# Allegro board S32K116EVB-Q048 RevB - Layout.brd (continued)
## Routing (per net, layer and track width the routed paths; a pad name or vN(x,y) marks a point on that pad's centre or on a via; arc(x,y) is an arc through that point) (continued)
XTAL: length 6.6
  TOP w0.16: Y3.2 57.34,26.25 57.82,25.77 C127.1 59.17,25.77 R91.2 R84.1
N20108236: length 2.2
  TOP w0.16: R737.1 39.52,35.43 38.99,34.91 U15.5
N20187731: length 2.1
  TOP w0.16: D11.A3 109.26,15.43 109.18,15.51 R95.1
N20187747: length 2.1
  TOP w0.16: R96.1 111.34,15.45 111.36,15.43 D11.A2
N20224636: length 10.2
  TOP w0.16: R597.1 C5.1 107.66,46.27 108.29,46.9 110.02,46.9 R13.2 108.41,43.98 TP5.1
N20296072: length 11
  TOP w0.16: R596.1 109.56,32.55 R44.1 SW2.3 SW2.1 112.27,38.78 112.23,38.82 TP532.1
N20296289: length 10.8
  TOP w0.16: R595.1 109.55,25.82 R74.1 SW3.1 ; SW3.1 SW3.3 ; SW3.1 112.27,26.96 112.23,27 TP531.1
N20296614: length 2.1
  TOP w0.16: D11.A1 113.46,15.43 113.5,15.47 R97.1
N20342040: length 5.5
  TOP w0.16: R712.2 R717.2 28.73,50.16 27.71,51.18 27.71,52.17 J2.10
N20342083: length 7.1
  TOP w0.16: J2.9 32.27,52.57 32.67,52.57 33.28,51.96 33.28,50.69 R719.2 R716.2 R713.2
N20408163: length 3.4
  TOP w0.203: TP540.1 33.11,32.68
  TOP w0.254: 33.11,32.68 R169.2 R170.2 35.17,32.71 U15.3
N20408770: length 1.6
  TOP w0.16: U15.4 40.06,32.71 40.06,32.71 C59.1
N20447644: length 3.5
  TOP w0.16: R675.2 73.68,51.38 73.62,51.45 J1.1
N20447648: length 3.9
  TOP w0.16: J1.2 72.16,52.3 R676.2
N20483097: length 2.5
  TOP w0.16: R715.2 J3.5
N20487701: length 2.6
  TOP w0.16: R527.1 SW8.1
N20498073: length 24.1
  TOP w0.203: v1(14.9,18.24) U19.15
  TOP w0.254: v1(33.74,19.98) 33.68,19.91 Q1.4
  BOTTOM w0.254: v1(14.9,18.24) 14.9,18.23 17.37,18.23 20.47,21.34 21.98,21.34 21.99,21.34 22.29,21.34 23.65,19.98 v1(33.74,19.98)
N20519466: length 3.5
  TOP w0.254: U19.13 15.88,19.24 15.87,19.25 14.95,19.25 TP544.1
  TOP w0.381: TP544.1 14.66,18.96 C536.1
N20529258: length 7.9
  TOP w0.508: D6.C 14.03,26.33 13.49,25.78 13.49,23.33 12.98,22.82 R171.2 R80.2
N20532266: length 36
  TOP w0.254: TP523.1 28.6,14.52 ; TP523.1 27.56,14.98 ; TP523.1 28.5,14.05 ; TP523.1 28.5,14.98 ; TP523.1 28.03,15.09 ; TP523.1 27.56,14.05 ; TP523.1 27.46,14.52
  TOP w0.305: 22.43,18.83 21.84,18.24 U19.6
  TOP w0.381: 22.88,18.88 R535.2 ; R535.2 22.88,19.52 ; R535.2 23.84,18.88 ; R535.2 24.79,19.52 ; R535.2 24.79,18.88
  TOP w0.635: Q1.5 30.64,20.38 ; Q1.5 28.05,15.62 ; Q1.5 30.64,18 ; Q1.5 25.46,15.63 ; Q1.5 25.46,20.38 ; Q1.5 28.05,20.39 ; Q1.5 30.64,15.63 ; Q1.5 25.46,18
  vias: v1(28.98,21.46)
N20533540: length 2.6
  TOP w0.16: R172.1 SW7.1
N20537015: length 24
  TOP w0.16: v1(9.61,13.36) C551.1 9.61,11.01 R537.2 SW9.1 SW9.3 2.15,11.88 TP518.1 ; U19.12 15.84,19.74 15.48,20.1 v1(14.95,20.1)
  L3_INT_1 w0.165: v1(9.61,13.36) 11.73,13.36 12.85,14.48 12.85,18.01 v1(14.95,20.1)
N20537534: length 3.6
  TOP w0.16: J108.1 17.38,21.93 D6.A
N20615858: length 2.7
  TOP w0.16: R612.2 R590.1 39.35,25.84 U26.6
N20615860: length 3
  TOP w0.16: U26.7 R589.1 38.19,27.22 R613.2
N20628442: length 2.4
  TOP w0.16: U32.7 R585.1 44.23,24.3 43.6,24.93 R616.2
N20629726: length 1.3
  TOP w0.16: U32.2 43.88,20.63 R577.2
N20726302: length 1.5
  TOP w0.16: U32.3 44.28,21.25 44.33,21.21 R578.2
N20727622: length 4.8
  TOP w0.16: v1(45.94,22.9) 45.55,22.52 U32.5 ; v1(43.21,23.09) 42.89,23.41 R562.2
  BOTTOM w0.16: v1(43.21,23.09) 43.4,22.9 v1(45.94,22.9)
N20728836: length 10.1
  TOP w0.16: C40.1 8.85,19.85 8.47,20.23 R92.2 5.63,20.23 5.22,19.82 5.22,16.93 5.73,16.42 R98.1
N20751108: length 1.4
  TOP w0.16: U33.5 R571.2
N20751111: length 2.4
  TOP w0.16: R610.2 49.24,24.93 R587.1 U33.7
N20751112: length 2.4
  TOP w0.16: U33.6 50.27,23.68 R588.1 R611.2
N20754157: length 1.4
  TOP w0.16: R572.2 40.6,24.68 U26.5
N20757133: length 2.1
  TOP w0.16: R615.2 R591.1 U34.7
N20757185: length 2.4
  TOP w0.16: U34.6 39.6,20 R592.1 R614.2
N20757257: length 1.2
  TOP w0.16: R576.2 U34.5
N20757373: length 2.7
  TOP w0.16: R617.2 R579.2 49.47,20.76 U33.2
N20757398: length 2.5
  TOP w0.16: U33.3 49.87,21.35 50.48,20.74 R580.2 50.63,20.61 R618.2
N20757820: length 3.4
  TOP w0.16: U26.2 38.55,23.64 38.37,23.46 37.38,23.46 R619.2 36.92,23.03 R581.2
N20757845: length 4
  TOP w0.16: U26.3 38.95,23.48 38.82,23.36 R582.2 39.71,22.9 40.6,23.79 R620.2
N20758005: length 2.7
  TOP w0.16: R621.2 37.68,17.82 R583.2 38.8,17.42 U34.2
N20758031: length 2.6
  TOP w0.16: U34.3 39.2,17.31 R584.2 40.04,17.06 40.27,17.28 R622.2
N20759089: length 1.4
  TOP w0.457: R56.2 D3.A
N20766439: length 4.5
  TOP w0.16: J14.6 80.83,45.9 80.63,46.1 R573.2 79.35,45.8 79.35,45.59 78.71,44.96 R119.1
N20766441: length 4.1
  TOP w0.16: R623.2 R120.1 80.59,47.73 81.15,47.17 J14.8
N20788275: length 3.8
  TOP w0.16: TPAD93.1 92.88,2.37 92.88,2.66 R598.2 R599.1 95.05,3.21 95.06,3.21 Q6.1
N20788431: length 3.4
  TOP w0.16: TPAD96.1 93.27,5.33 R601.2 R600.1 94.97,5.5 94.98,5.49 Q7.1
N20788562: length 4.8
  TOP w0.16: R603.2 R602.1 94.97,8.04 94.98,8.03 Q8.1 95.72,8.17 TPAD98.1
N20797138: length 3.9
  TOP w0.457: R605.1 47.21,15.4 Q9.1 48.34,16.05 48.48,16.19 TPAD100.1
  TOP w0.635: TPAD100.1 R604.2
N20798434: length 1.8
  TOP w0.457: Q9.3 49.63,14.38 D3.C
N20799004: length 4.1
  TOP w0.635: R606.1 v1(5.93,18.2)
  L3_INT_1 w0.635: J13.3 2.87,18.2 v1(5.93,18.2)
N20829527: length 2.1
  TOP w0.635: U15.1 36.66,34.61 37.3,35.25 R624.2
N20881340: length 4.9
  TOP w0.508: R674.2 107.99,51.47 R13.1
N20904035: length 25.5
  TOP w0.127: 74.28,24.38 U36.19
  TOP w0.16: R711.1 R740.1 v1(81.33,37.46) ; R739.1 v1(74.6,22.56) 74.14,23.02 74.14,23.66 74.28,23.8 74.28,24.38
  L3_INT_1 w0.165: v1(76.83,36.2) 76.48,35.84 76.48,24.86 75.89,24.28 75.89,23.8 74.65,22.56 v1(74.6,22.56)
  BOTTOM w0.16: v1(76.83,36.2) 80.06,36.2 v1(81.33,37.46)
N20906563: length 5.3
  TOP w0.16: J4.13 76.16,6.77 R685.2 R743.2
N20906569: length 4.8
  TOP w0.16: J4.11 73.62,6.41 R686.2
N20906587: length 4.9
  TOP w0.16: J4.5 64.67,6.45 64.67,8 63.65,9.02
N20906597: length 5.5
  TOP w0.16: J4.3 63.46,7.05 R742.2 R745.2
N20906792: length 40.7
  TOP w0.16: J4.15 78.7,4.26 77.68,3.24 77.68,2.16 78.28,1.56 80.45,1.56 81.18,2.29 81.18,5.33 83.21,7.37 83.21,9.02 v1(84.25,9.02) ; R681.2 84.21,31.41 v1(84.95,31.41)
  L3_INT_1 w0.165: v1(84.25,9.02) 83.64,9.63 83.64,19.91 82.95,20.6 82.95,24.82 84.95,26.81 v1(84.95,31.41)
N20910223: length 7.5
  TOP w0.16: 68.86,9.02 68.86,8.25 70,7.11 70,4.04 J4.8
N20910227: length 7.5
  TOP w0.16: R702.2 65.75,7.43 67.08,6.1 67.08,3.66 J4.6
N20911130: length 7.9
  TOP w0.16: R693.2 74.76,6.39 74.76,3.72 J4.12
N20911135: length 7.3
  TOP w0.16: J4.14 77.43,3.85 77.43,7.05 76.29,8.19 R694.2
N20911140: length 7.5
  TOP w0.16: J4.16 79.97,3.85 79.97,7.4 R695.2
N20917588: length 3.9
  TOP w0.16: J3.2 36.91,3.73 R754.2
N20917593: length 5.8
  TOP w0.16: R753.2 41.1,6.73 41.88,5.94 41.88,3.86 J3.4
N20917620: length 5.7
  TOP w0.16: R752.2 54.38,3.65 J3.14
N20992665: length 1.5
  TOP w0.16: R729.1 4.21,54.1 3.95,53.83 D1.A
N20992701: length 4.5
  TOP w0.16: R731.1 10.56,48.92 10.59,48.89 R730.1 10.59,47.57 10.72,47.45 10.72,46.61 10.54,46.43 9.35,46.43 9.18,46.6 Q10.3
N20992723: length 5.5
  TOP w0.16: R732.2 R733.2 12.57,45.09 11.81,44.32 9.93,44.32 9.68,44.58 Q10.5
N20992733: length 4.7
  TOP w0.16: Q11.2 7.19,45.77 9.42,48.01 R730.2 9.57,48.92 R734.1
N207179701: length 1.4
  TOP w0.635: C544.2 C545.1
N207665286: length 2.3
  TOP w0.16: J14.7 86.06,47.17 TP542.1
N207665288: length 2.3
  TOP w0.16: TP543.1 86.06,48.44 J14.9

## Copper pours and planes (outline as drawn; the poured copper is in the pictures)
GND on TOP: 0.77,39.01 2.27,39.01 2.68,39.43 2.68,42.28 2.37,42.6 0.77,42.6 0.76,45.34 2.46,45.34 2.67,45.55 2.67,47.11 2.51,47.27 0.76,47.27 0.76,49.53 3.14,55.28 8.89,57.66 106.71,57.66 112.45,55.28 114.83,49.53 114.83,8.89 112.45,3.14 106.71,0.76 8.92,0.76 3.17,3.14 0.79,8.89 ; 82 cut-outs
GND on BOTTOM: 0.77,39.01 2.27,39.01 2.68,39.43 2.68,42.28 2.37,42.6 0.77,42.6 0.76,45.34 2.46,45.34 2.67,45.55 2.67,47.11 2.51,47.27 0.76,47.27 0.76,49.53 3.14,55.28 8.89,57.66 79.2,57.66 79.2,52.55 79.6,52.15 103.08,52.15 103.09,52.16 104.08,52.16 108.17,48.07 108.17,11.57 106.29,9.7 89.2,9.7 85.38,5.88 81.75,5.88 81.75,2.03 64.06,2.03 63.88,1.85 63.88,0.76 8.92,0.76 3.17,3.14 0.79,8.89 ; 39 cut-outs
GND on L2_GND_1, L4_INT_2, L5_GND_2: 0.77,39.01 2.27,39.01 2.68,39.43 2.68,42.28 2.37,42.6 0.77,42.6 0.76,45.34 2.46,45.34 2.67,45.55 2.67,47.11 2.51,47.27 0.76,47.27 0.76,49.53 3.14,55.28 8.89,57.66 106.71,57.66 112.45,55.28 114.83,49.53 114.83,8.89 112.45,3.14 106.71,0.76 8.92,0.76 3.17,3.14 0.79,8.89
GND on L3_INT_1: 8.92,0.76 3.17,3.14 0.79,8.89 0.77,40.65 2.43,40.65 2.98,41.2 2.98,42.4 2.73,42.65 0.77,42.65 0.76,45.25 2.3,45.25 2.87,45.81 2.87,47.45 2.54,47.77 0.76,47.77 0.76,48.83 1.13,48.83 1.13,50.3 0.8,50.3 3.42,55.54 8.89,57.66 106.71,57.66 112.45,55.28 114.83,49.53 114.83,8.89 112.45,3.14 106.71,0.76 ; 24 cut-outs
P3V3 on TOP: 38.55,27.07 38.19,27.43 38.19,35.34 39.39,35.34 39.61,35.56 41.21,35.56 41.43,35.34 45.74,35.34 45.74,27.91 44.9,27.07
P3V3 on L3_INT_1: 39.97,26.45 39.97,22.77 42,20.74 42,15.02 46.7,10.33 46.7,4.61 46.19,4.1 42,4.1 42,7.66 36.03,13.63 36.03,18.2 35.63,18.59 35.63,21.23 36.03,21.63 36.03,26.07 38.44,28.49 38.44,31.03 39.08,31.66 45.3,31.66 45.68,31.28 45.68,27.34 45.05,26.71 40.22,26.71
P3V3_SDA on TOP: 8.44,51.41 9.32,51.41 9.4,51.49 9.4,52.17 9.6,52.37 10.03,52.37 10.23,52.17 10.23,51.23 10.09,51.08 10.09,49.5 8.71,49.5 8.34,49.87 8.34,50.67 8.44,50.76
P3V3_SDA on TOP: 31.33,37.21 31.33,35.22 30.44,34.33 30.06,34.33 30.06,37.25 31.29,37.25
P3V3_SDA on BOTTOM: 28.54,36.36 28.3,36.6 28.3,38.09 28.05,38.34 27.28,38.34 27.09,38.53 27.09,41.66 28.25,42.82 28.25,44.74 27.93,45.07 26.22,45.07 24.24,47.04 24.24,48.22 23.48,48.98 16.32,48.98 16.14,48.81 16.14,46.85 16.37,46.63 17.54,46.63 19.85,44.32 19.85,43.08 19.22,42.46 16.84,44.84 14.48,44.84 13.48,43.84 13.48,37.34 11.86,35.72 11.86,31.77 12.24,31.39 13.58,31.39 13.58,33.98 16.27,36.67 16.27,38.06 16.44,38.23 16.92,38.23 16.92,36.23 14.57,33.88 14.57,33.87 14.31,33.62 14.31,28.65 14.57,28.39 18.69,28.39 18.11,27.81 16.53,27.81 15.52,26.8 11.07,26.8 10.59,27.28 10.59,47.9 9.07,49.43 7.59,49.43 6.63,50.39 6.63,53.98 7.39,54.74 9.93,54.74 10.11,54.56 10.11,52.63 12.17,50.57 25.55,50.57 30.44,45.69 30.44,44.44 30.42,44.43 30.42,44.36 31.38,43.4 31.38,42.64 31.09,42.35 29.27,42.35 29.27,39.96 31.36,39.96 34.29,42.89 37.86,42.89 37.86,41.58 35.63,41.58 35.21,41.16 35.21,39.28 34.91,38.97 34.91,38.67 32.6,36.36 ; 1 cut-out
P5V0 on BOTTOM: 23.85,34.37 28.15,34.37 28.53,33.99 42.69,33.99 42.69,26.39 42.89,26.2 42.89,25.57 42.76,25.44 40.09,25.44 37.81,27.72 30.47,27.72 30.47,31.07 26.49,31.07 26.49,26.33 23.85,26.33
P5V0 on L3_INT_1: 45.81,26.33 45.94,26.2 45.94,23.66 47.08,22.52 48.96,22.52 50.25,21.22 50.25,19.92 51.14,19.04 51.14,12.03 52.43,10.74 52.43,4.29 52.24,4.1 47.03,4.1 47.03,11.01 42.89,15.15 42.89,20.87 40.22,23.53 40.22,26.33
P5V_SBC on TOP: 43.4,24.04 43.4,21.63 42.56,20.79 37.02,20.79 36.37,21.45 34.28,21.45 34.75,21.45 34.85,21.52 34.84,21.65 34.91,22.19 35.45,22.11 35.58,22.11 35.67,22.24 35.8,22.34 35.8,22.39 35.78,22.43 35.74,22.45 35.53,22.53 35.38,22.69 35.27,22.76 35.16,22.69 34.99,22.52 34.76,22.45 34.28,22.45 34.28,25.92 37.89,25.92 37.89,22.77 39.84,22.77 42,24.93 42.51,24.93 ; 1 cut-out
P5V_SBC on BOTTOM: 50.51,21.5 51.46,20.55 52.35,20.55 52.54,20.74 52.54,23.76 50.36,23.76 50.03,23.44 38.57,23.44 36.16,25.86 36.16,26.14 30.3,26.14 30.3,30.89 26.69,30.89 26.69,22.87 31.3,22.87 31.84,23.41 37.3,23.41 38.7,22.01 42.13,22.01 42.63,21.5 ; 1 cut-out
P5V_SDA on L3_INT_1: 7.34,28.63 12.02,28.63 14.14,30.75 14.14,33.95 14.62,34.43 25.57,34.43 27.16,36.02 27.16,44.62 25.57,46.22 16.22,46.22 14.31,44.31 14.31,44.36 10.5,40.55 7.48,40.55 6.54,39.61 6.54,29.43
VBATT on TOP: 24.35,12.74 25.36,13.75 30.31,13.75 30.57,13.5 30.57,10.58 30.31,10.33 26.5,10.33 26.12,9.94 26.12,7.58 27.19,6.52 39.28,6.52 39.54,6.26 39.54,4.36 40.12,3.77 53.61,3.77 54.44,4.61 54.44,8.98 54.65,9.18 57.14,9.18 57.87,8.45 57.87,1.82 56.86,0.8 27.93,0.8 21.07,7.66 21.07,12.51 21.3,12.74 ; 1 cut-out
VBATT on L3_INT_1: 8.53,13.34 7.96,13.91 7.96,15.81 10.82,18.67 10.82,27.3 9.8,28.32 7.14,28.32 6.25,29.21 6.25,33.4 5.1,34.54 0.79,34.54 0.79,11.05 6.63,5.21 25.8,5.21 25.8,13.13 25.6,13.34
VDD on TOP: 45.76,28.6 45.76,35.51 45.43,35.84 41.36,35.84 41.36,37 41.24,37.12 39.81,37.12 39.81,38.45 40.38,39.02 40.38,39.05 40.53,39.19 40.53,42.93 41.67,44.07 47.01,44.07 47.9,44.96 47.9,57.53 81.43,57.53 81.43,53.64 79.48,51.69 79.48,51.33 79.5,51.31 79.5,43.26 80.87,41.88 82.22,41.88 83.08,42.75 83.08,43.71 83.41,44.04 85.72,44.04 85.88,43.89 85.88,40.56 84.89,39.57 84.86,39.57 84.15,38.86 80.95,38.86 77.49,42.32 77.49,43.61 77.11,43.99 77.11,53.21 75.84,54.48 57.81,54.48 57.3,53.98 57.3,49.02 54.38,46.1 54.38,35.56 51.5,32.68 49.24,32.68 48.7,32.14 48.7,28.6 ; 1 cut-out
VDD on BOTTOM: 64.35,1.78 91.62,1.78 93.43,3.59 105.63,3.59 112.99,10.96 112.99,49.82 108.93,53.89 104.48,53.89 103.34,52.74 103.31,52.74 102.98,52.41 100.12,52.41 100.1,52.4 79.71,52.4 79.45,52.65 79.45,57.32 107.89,57.32 107.93,57.28 108.79,57.28 114.4,51.66 114.4,9.61 105.52,0.72 64.35,0.72
VDD on L3_INT_1: 72.4,3.86 72.4,0.72 26,0.72 26,8.19 26.05,8.23 26.05,26.25 26.12,26.33 26.12,27.6 39.97,41.44 40.03,41.44 40.03,41.66 40.66,42.29 40.66,44.07 39.14,45.59 36.35,45.59 32.92,49.02 27.46,49.02 25.3,51.18 7.14,51.18 6.25,50.29 6.25,47.12 6.63,46.74 12.06,46.74 12.57,46.23 12.57,45.31 12.22,44.96 3.71,44.96 2.84,45.82 2.84,47.37 2.44,47.77 0.76,47.77 0.76,47.78 0.76,48.83 1.13,48.83 1.13,50.3 0.8,50.3 3.42,55.54 8.89,57.66 24.53,57.66 25.3,56.9 25.3,52.32 25.8,51.82 27.33,51.82 28.6,50.55 34.19,50.55 35.33,49.4 38.25,49.4 38.38,49.53 45.74,42.16 45.74,41.53 45.55,41.34 45.68,41.21 45.68,32.7 45.02,32.04 39.08,32.04 38.06,31.03 38.13,30.96 38.13,28.68 32.11,22.66 32.11,6.67 34.91,3.86
VDD_MCU on TOP: 48.8,27.24 51.8,27.24 62.19,37.63 62.19,39.03 63.33,40.17 63.97,40.17 64.48,40.68 64.48,43.6 64.86,43.98 64.86,44.49 64.73,44.62 63.33,44.62 63.08,44.36 63.08,42.33 62.32,41.57 56.48,41.57 56.43,41.52 54.87,41.52 54.63,41.27 54.63,35.34 52.06,32.77 49.33,32.77 48.98,32.42 48.98,28.52 45.97,28.52 45.85,28.4 45.85,25.8 47.36,25.8
VDD_PERH on TOP: 51.02,14.87 51.02,12.76 51.3,12.48 55.97,12.48 56.35,12.87 56.35,15.05 56.12,15.28 51.42,15.28
VDD_PERH on BOTTOM: 108.42,48.17 108.42,11.47 106.41,9.46 89.78,9.46 85.94,5.63 82,5.63 82,2.03 91.24,2.03 93.05,3.85 105.63,3.85 112.61,10.83 112.61,49.57 108.67,53.51 104.93,53.51 104.93,51.67
VDDA_MCU on TOP: 64.73,39.92 64.35,39.54 64.35,37.5 64.73,37.12 68.54,37.12 68.92,37.5 69.3,37.5 71.27,39.47 71.27,41.57 71.14,41.69 68.41,41.69 68.4,41.71 66.5,41.71 66,42.2 66,43.35 65.75,43.6 64.86,43.6 64.6,43.35 64.6,40.55 64.73,40.42
SDA_USBSHIELD on TOP (solid shape): 2.4,48.27 5.07,48.27 5.07,46.25 3.83,46.25 3.83,47.25 0.5,47.25 0.5,48.98 2.4,48.98
SDA_USBSHIELD on TOP (solid shape): 5.07,39.78 2.4,39.78 2.4,39.07 0.5,39.07 0.5,40.8 3.83,40.8 3.83,41.8 5.07,41.8
V_TGTMCU on TOP: 2.36,51.31 5.1,51.31 5.1,51.3 5.61,51.3 5.87,51.05 5.87,49.91 6.25,49.53 6.25,49.15 6.91,48.49 8,48.49 8.09,48.4 8.09,47.8 8.08,47.8 7.92,47.65 6.68,47.65 6.53,47.8 5.69,47.8 5.48,48.01 5.48,48.39 5.36,48.51 3.45,48.51 2.36,49.61
V_TGTMCU on L3_INT_1: 13.36,50.42 13.56,50.61 25.42,50.61 27.14,48.89 33.15,48.89 35.79,46.26 39.87,46.26 39.87,46.24 40.12,45.99 40.12,42.45 38.69,41.02 38.56,40.84 32.92,40.84 30.35,38.27 28.8,38.27 28.8,46.25 28.47,46.58 11.83,46.58 11.83,46.61 11.58,46.61 11.2,46.99 6.88,46.99 6.63,47.24 6.63,50.16 6.88,50.42
VSUP on TOP: 31.58,19.02 37.47,19.02 37.47,14.66 39.32,14.66 39.46,14.52 39.46,10.45 31.58,10.45
VSUP on BOTTOM: 18.66,23.84 18.57,23.75 17.42,23.75 16.1,22.43 16.1,18.52 14.44,18.52 14.44,14.56 35.78,14.56 35.78,11.98 35.01,11.21 30.44,11.21 29.3,12.36 13.69,12.36 12.39,11.06 12.39,9.6 10.85,9.6 10.73,9.72 10.73,12.4 12.15,13.83 12.15,24.14 12.28,24.27 16.04,24.27 16.15,24.38 16.15,25.27 17.04,26.16 18.82,26.16 19.07,25.91 19.07,24.89 18.66,24.48
N20532266 on TOP: 30.99,13.93 30.99,21.83 25.71,21.83 24.07,20.18 22.87,20.18 22.87,19.75 22.24,19.12 22.24,18.48 25.06,18.48 25.06,13.93

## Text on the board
BOTTOM: 170-30003 REV B | 9 OF 12 | L6_SS
Board Geometry/Soldermask Bottom: 10 OF 12 | SECONDARY SOLDERMASK
Ref Des/Silkscreen Bottom: GND | LIN | VBAT | CAN_HI | CAN_LO | VDD | OpenSDA | J3 | VABTT | PTB0 | VDD_PERH | PTB1 | PTB6 | RESET | 3.3V | PTB7 | PTA1 | 5V | PTE4 | PTA0 | PTE5 | AREF | PTA10 | PTD3 | PTB2 | PTB3 | PTB4 | PTB5 | PTC3 | PTC2 | J4 | J2 | PTA6 | PTC6 | PTC0 | PTC7 | PTC1 | PTC8 | PTC14 | PTC9 | PTD5 | PTC15 | PTE9 | PTC16 | PTD15 | PTD2 | PTC17 | PTD16 | PTD1 | PTB13 | PTE8 | PTD0 | PTA12 | PTA13 | PTA3 | PTA2 | J1 | S32K116EVB-Q048 | 11 OF 12 | SECONDARY SILKSCREEN | 700
User.Comments: 1 OF 1 | TEST PROBE | 1/1 | 1
TOP: 4 OF 12 | L1_PS
Board Geometry/Soldermask Top: 3 OF 12 | PRIMARY SOLDERMASK
Ref Des/Silkscreen Top: CAN | LIN | SBC_IO | VSUP | RESET | E | I | GND | c | SWD_DIO | G | M | J | VDD_MCU | VDD | K | L | VDD_PERH | VDDA_MCU | S32K | H | ADC_POT | B | R | A | LO | HI | PWR IN (5-12V) | OPENSDA | VBAT | P5V0 | P3V3 | * | # | TOUCH ELECTRODES | S32K116EVB-Q048 | 2 OF 12 | PRIMARY SILKSCREEN
L2_GND_1: 5 OF 12 | L2_GND_1
L3_INT_1: 6 OF 12 | L3_INT_1
L4_INT_2: 7 OF 12 | L4_INT_2
L5_GND_2: 8 OF 12 | L5_GND_2
DIMENSION: PRIMARY DATUM | GRID ORIGIN
BODY_CENTER: 22. | (1220.00 1285.00)    SH1       V_TGTMCU        &         VDD | INTENTIONAL SHORTS AT: | Location           RefDes      Net 1                  Net 2 | 16 | LAYER 5  L5_GND_2    1 oz. | LAYER 6  L6_SS       1/2 to 1 oz | 17 | 8
PASTEMASK_TOP: 1 OF 12 | PASTEMASK TOP
User.5: 12 OF 12 | SECONDARY PASTEMASK
User.14: 01-30-18 | R.O. | B
User.17: L6_SS | 6.30 | 50 | X.XX | 90
User.23: FIGURE | SIZE | 10.0 | 14.0 | 15.0 | 31.0 | 40.0 | 63.0 | 100.0 | 125.0 | 34.0x26.0 | 60.0x33.0 | 111.0x32.0 | 122.0x32.0 | ECO79865 CHANGES | DRILL CHART: TOP to BOTTOM | ALL UNITS ARE IN MILS | TOLERANCE | +0.0/-10.0 | +0.0/-14.0 | +2.0/-2.0 | +3.0/-3.0 | PLATED | NON-PLATED | QTY | 601 | 27 | 2 | 20 | 74 | 9 | 1 | 4 | 3
